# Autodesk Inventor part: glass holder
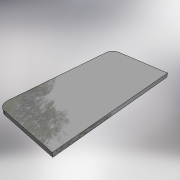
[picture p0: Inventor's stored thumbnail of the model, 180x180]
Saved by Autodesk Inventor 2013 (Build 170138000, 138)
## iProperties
Shininess: 64.0
Length Units: 11269
Angle Units: 11279
Time Units: 11290
Mass Units: 11283
Length Display Precision: 3
Angle Display Precision: 2
Compacted: True
Part Number: glass holder
Document SubType Name: Листовой материал
Created: 2005-02
Material: Stainless Steel, 440C
Designer: =<Author>
Manufacturer: Standard
Standards Organization: Custom
Description: =<Part Number>
Density: 7.75 g/cm^3
Sheet Metal Rule: По умолчанию
Mass: 89.6648 g
Surface Area: 84.8965 cm^2
Volume: 11.5696 cm^3
Density: 0.0
Volumn: 0.0
Area: 0.0
PropertySet Name: Model Information
Control State: 0
Master: False
Checked Out: False
Checked Out Date: 2008-10-15
Last Check In Date: 2008-10-15
Толщина: 3.000 mm
Радиус_гибки: 3.000 mm
Ширина_просечки: 3.000 mm
Глубина_просечки: 1.500 mm
Размер_высечки: 12.000 mm
Минимальный_остаток: 6.000 mm
Радиус_перехода: 3.000 mm
JacobiRadiusSize: 3.000 mm
GapSize: 3.000 mm
d0: 88.000 mm
d1: 44.000 mm
d2: 3.000 mm
d3: 6.000 mm
Author: PVitaliy
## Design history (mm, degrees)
node "Грань1"
feature "УглСкругление1" dims "d3" = 6
body "Solid1"
sketch "Эскиз1"
  geometry: L1 (0, 0)-(44, 0); L2 (44, 0)-(44, 88); L3 (44, 88)-(0, 88); L4 (0, 88)-(0, 0)
  constraints: 8 end point, 2 parallel, 1 horizontal, 1 perpendicular, 1 other
  dimensions: "d0" = 88 distance of L3.end L1.start; "d1" = 44 distance of L1.start L1.end
feature "Пластина1" dims "Толщина" = 3
other parameters: "Радиус_гибки" = 3 (= Толщина), "Ширина_просечки" = 3 (= Толщина), "Глубина_просечки" = 1.5 (= 0.5 x Толщина), "Размер_высечки" = 12 (= 4 x Толщина), "Зазор_стыка" = 0.01, "Минимальный_остаток" = 6 (= 2 x Толщина), "Радиус_перехода" = 3 (= Радиус_гибки), "d2" = 3 (= Радиус_гибки), "JacobiRadiusSize" = 3 (= Толщина), "GapSize" = 3 (= Толщина)
